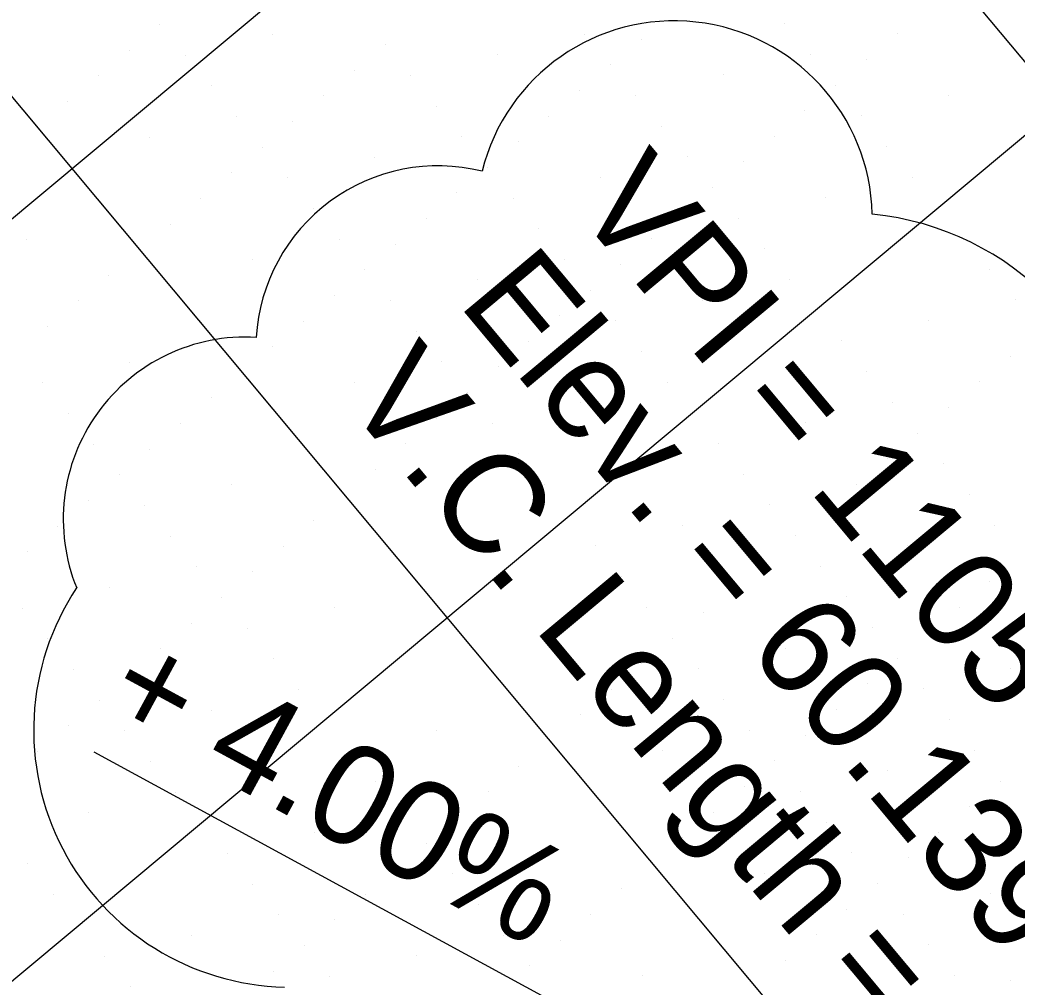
# Model space of a CAD drawing. Extents: x 2042995 to 2043795, y 305365 to 306249.
# Drawn here: x 2043332.63 to 2043357.56, y 305814.05 to 305838.24 of the extents above; entities that cross this region are included whole.
import ezdxf

# ---------------------------------------------------------------- set-up
doc = ezdxf.new("R2010")
doc.units = 0
for name, color, linetype in [('BR_CENTER LINES', 7, 'Continuous'), ('BR_CONCRETE', 7, 'Continuous'), ('BR_GRID DOTS', 7, 'Continuous'), ('BR_GRID LINES', 7, 'Continuous'), ('BR_PRESTRESSED BEAM', 7, 'Continuous'), ('BR_SITE LOCATION', 7, 'Continuous'), ('BR_TABLE LINES', 7, 'Continuous'), ('BR_TEXT', 7, 'Continuous')]:
    doc.layers.add(name, color=color, linetype=linetype)

msp = doc.modelspace()

# ---------------------------------------------------------------- linework, layer by layer
at = {"layer": 'BR_CENTER LINES'}
msp.add_line((2043349.78, 305847.751), (2043253.934, 305767.702), dxfattribs=at)
at = {"layer": 'BR_CONCRETE'}
for points in [[(2043139.109, 306017.548), (2043148.199, 306007.16), (2043160.233, 305993.368), (2043172.245, 305979.557), (2043184.234, 305965.727), (2043196.201, 305951.879), (2043208.145, 305938.012), (2043220.067, 305924.126), (2043231.966, 305910.221), (2043243.843, 305896.297), (2043255.698, 305882.355), (2043267.529, 305868.394), (2043279.339, 305854.414), (2043291.126, 305840.415), (2043302.89, 305826.398), (2043314.632, 305812.361), (2043326.352, 305798.306), (2043338.049, 305784.233), (2043349.724, 305770.14), (2043361.376, 305756.029), (2043373.005, 305741.899), (2043384.613, 305727.75), (2043396.197, 305713.582), (2043407.76, 305699.396), (2043419.299, 305685.191), (2043430.817, 305670.967), (2043442.311, 305656.724), (2043453.784, 305642.463), (2043465.234, 305628.182), (2043476.661, 305613.883), (2043488.066, 305599.566), (2043499.448, 305585.229), (2043510.808, 305570.874), (2043522.146, 305556.5), (2043533.461, 305542.107), (2043544.753, 305527.695), (2043547.219, 305524.543)], [(2043273.14, 305860.139), (2043278.86, 305853.362), (2043290.647, 305839.364), (2043302.411, 305825.346), (2043314.153, 305811.31), (2043325.873, 305797.255), (2043337.57, 305783.181), (2043349.245, 305769.089), (2043360.897, 305754.977), (2043372.526, 305740.847), (2043384.134, 305726.698), (2043395.718, 305712.531), (2043407.281, 305698.344), (2043418.82, 305684.139), (2043425.623, 305675.744)]]:
    msp.add_spline(points, degree=3, dxfattribs=at)
at = {"layer": 'BR_GRID DOTS'}
for p, q in [((2043336.123, 305838.127), (2043336.123, 305838.127)), ((2043351.743, 305838.144), (2043351.743, 305838.144)), ((2043338.94, 305837.874), (2043338.94, 305837.874)), ((2043346.75, 305837.883), (2043346.75, 305837.883)), ((2043354.561, 305837.892), (2043354.561, 305837.892)), ((2043341.757, 305837.621), (2043341.757, 305837.621)), ((2043348.159, 305837.756), (2043348.159, 305837.756)), ((2043335.355, 305837.486), (2043335.355, 305837.486)), ((2043336.764, 305837.36), (2043336.764, 305837.36)), ((2043344.574, 305837.368), (2043344.574, 305837.368)), ((2043352.385, 305837.377), (2043352.385, 305837.377)), ((2043347.391, 305837.115), (2043347.391, 305837.115)), ((2043353.793, 305837.25), (2043353.793, 305837.25)), ((2043334.588, 305836.845), (2043334.588, 305836.845)), ((2043340.99, 305836.98), (2043340.99, 305836.98)), ((2043342.398, 305836.854), (2043342.398, 305836.854)), ((2043350.208, 305836.862), (2043350.208, 305836.862)), ((2043337.405, 305836.592), (2043337.405, 305836.592)), ((2043353.026, 305836.609), (2043353.026, 305836.609)), ((2043340.222, 305836.339), (2043340.222, 305836.339)), ((2043346.624, 305836.474), (2043346.624, 305836.474)), ((2043348.032, 305836.348), (2043348.032, 305836.348)), ((2043355.843, 305836.356), (2043355.843, 305836.356)), ((2043333.82, 305836.204), (2043333.82, 305836.204)), ((2043343.039, 305836.086), (2043343.039, 305836.086)), ((2043338.046, 305835.825), (2043338.046, 305835.825)), ((2043345.856, 305835.833), (2043345.856, 305835.833)), ((2043352.258, 305835.968), (2043352.258, 305835.968)), ((2043353.667, 305835.842), (2043353.667, 305835.842)), ((2043333.053, 305835.563), (2043333.053, 305835.563)), ((2043339.455, 305835.698), (2043339.455, 305835.698)), ((2043348.673, 305835.58), (2043348.673, 305835.58)), ((2043335.87, 305835.31), (2043335.87, 305835.31)), ((2043343.68, 305835.319), (2043343.68, 305835.319)), ((2043351.491, 305835.327), (2043351.491, 305835.327)), ((2043338.687, 305835.057), (2043338.687, 305835.057)), ((2043345.089, 305835.192), (2043345.089, 305835.192)), ((2043354.308, 305835.074), (2043354.308, 305835.074)), ((2043341.504, 305834.804), (2043341.504, 305834.804)), ((2043349.314, 305834.813), (2043349.314, 305834.813)), ((2043344.321, 305834.551), (2043344.321, 305834.551)), ((2043350.723, 305834.686), (2043350.723, 305834.686)), ((2043337.92, 305834.416), (2043337.92, 305834.416)), ((2043339.328, 305834.29), (2043339.328, 305834.29)), ((2043347.138, 305834.298), (2043347.138, 305834.298)), ((2043354.949, 305834.307), (2043354.949, 305834.307)), ((2043349.955, 305834.045), (2043349.955, 305834.045)), ((2043343.554, 305833.91), (2043343.554, 305833.91)), ((2043344.962, 305833.784), (2043344.962, 305833.784)), ((2043352.773, 305833.792), (2043352.773, 305833.792)), ((2043337.152, 305833.775), (2043337.152, 305833.775)), ((2043339.969, 305833.522), (2043339.969, 305833.522)), ((2043349.188, 305833.404), (2043349.188, 305833.404)), ((2043336.385, 305833.134), (2043336.385, 305833.134)), ((2043342.786, 305833.269), (2043342.786, 305833.269)), ((2043350.597, 305833.278), (2043350.597, 305833.278)), ((2043345.603, 305833.016), (2043345.603, 305833.016)), ((2043332.8, 305832.746), (2043332.8, 305832.746)), ((2043340.61, 305832.755), (2043340.61, 305832.755)), ((2043342.019, 305832.628), (2043342.019, 305832.628)), ((2043348.42, 305832.763), (2043348.42, 305832.763)), ((2043356.231, 305832.772), (2043356.231, 305832.772)), ((2043335.617, 305832.493), (2043335.617, 305832.493)), ((2043351.238, 305832.51), (2043351.238, 305832.51)), ((2043338.434, 305832.24), (2043338.434, 305832.24)), ((2043346.244, 305832.249), (2043346.244, 305832.249)), ((2043347.653, 305832.122), (2043347.653, 305832.122)), ((2043334.85, 305831.852), (2043334.85, 305831.852)), ((2043341.251, 305831.987), (2043341.251, 305831.987)), ((2043356.872, 305832.004), (2043356.872, 305832.004)), ((2043344.068, 305831.734), (2043344.068, 305831.734)), ((2043351.879, 305831.743), (2043351.879, 305831.743)), ((2043340.484, 305831.346), (2043340.484, 305831.346)), ((2043346.885, 305831.481), (2043346.885, 305831.481)), ((2043334.082, 305831.211), (2043334.082, 305831.211)), ((2043341.892, 305831.22), (2043341.892, 305831.22)), ((2043349.702, 305831.228), (2043349.702, 305831.228)), ((2043357.513, 305831.237), (2043357.513, 305831.237)), ((2043346.118, 305830.84), (2043346.118, 305830.84)), ((2043333.314, 305830.57), (2043333.314, 305830.57)), ((2043339.716, 305830.705), (2043339.716, 305830.705)), ((2043347.526, 305830.714), (2043347.526, 305830.714)), ((2043355.337, 305830.722), (2043355.337, 305830.722)), ((2043342.533, 305830.452), (2043342.533, 305830.452)), ((2043338.949, 305830.064), (2043338.949, 305830.064)), ((2043345.35, 305830.199), (2043345.35, 305830.199)), ((2043353.161, 305830.208), (2043353.161, 305830.208)), ((2043348.167, 305829.946), (2043348.167, 305829.946)), ((2043357.386, 305829.828), (2043357.386, 305829.828)), ((2043335.364, 305829.676), (2043335.364, 305829.676)), ((2043343.174, 305829.685), (2043343.174, 305829.685)), ((2043344.583, 305829.558), (2043344.583, 305829.558)), ((2043338.181, 305829.423), (2043338.181, 305829.423)), ((2043353.802, 305829.44), (2043353.802, 305829.44)), ((2043333.188, 305829.162), (2043333.188, 305829.162)), ((2043340.998, 305829.17), (2043340.998, 305829.17)), ((2043348.808, 305829.179), (2043348.808, 305829.179)), ((2043356.619, 305829.187), (2043356.619, 305829.187)), ((2043343.815, 305828.917), (2043343.815, 305828.917)), ((2043337.414, 305828.782), (2043337.414, 305828.782)), ((2043346.632, 305828.664), (2043346.632, 305828.664)), ((2043354.443, 305828.673), (2043354.443, 305828.673)), ((2043355.851, 305828.546), (2043355.851, 305828.546)), ((2043333.829, 305828.394), (2043333.829, 305828.394)), ((2043336.646, 305828.141), (2043336.646, 305828.141)), ((2043343.048, 305828.276), (2043343.048, 305828.276)), ((2043344.456, 305828.15), (2043344.456, 305828.15)), ((2043352.267, 305828.158), (2043352.267, 305828.158)), ((2043355.084, 305827.905), (2043355.084, 305827.905)), ((2043334.47, 305827.627), (2043334.47, 305827.627)), ((2043342.28, 305827.635), (2043342.28, 305827.635)), ((2043350.091, 305827.644), (2043350.091, 305827.644)), ((2043335.879, 305827.5), (2043335.879, 305827.5)), ((2043345.097, 305827.382), (2043345.097, 305827.382)), ((2043354.316, 305827.264), (2043354.316, 305827.264)), ((2043355.725, 305827.138), (2043355.725, 305827.138)), ((2043335.111, 305826.859), (2043335.111, 305826.859)), ((2043341.513, 305826.994), (2043341.513, 305826.994)), ((2043350.732, 305826.876), (2043350.732, 305826.876)), ((2043337.928, 305826.606), (2043337.928, 305826.606)), ((2043345.738, 305826.615), (2043345.738, 305826.615)), ((2043353.549, 305826.623), (2043353.549, 305826.623)), ((2043340.745, 305826.353), (2043340.745, 305826.353)), ((2043356.366, 305826.37), (2043356.366, 305826.37)), ((2043334.344, 305826.218), (2043334.344, 305826.218)), ((2043335.752, 305826.091), (2043335.752, 305826.091)), ((2043343.562, 305826.1), (2043343.562, 305826.1)), ((2043351.373, 305826.109), (2043351.373, 305826.109)), ((2043352.781, 305825.982), (2043352.781, 305825.982)), ((2043333.576, 305825.577), (2043333.576, 305825.577)), ((2043339.978, 305825.712), (2043339.978, 305825.712)), ((2043349.197, 305825.594), (2043349.197, 305825.594)), ((2043357.007, 305825.603), (2043357.007, 305825.603)), ((2043336.393, 305825.324), (2043336.393, 305825.324)), ((2043352.014, 305825.341), (2043352.014, 305825.341)), ((2043339.21, 305825.071), (2043339.21, 305825.071)), ((2043347.02, 305825.08), (2043347.02, 305825.08)), ((2043354.831, 305825.088), (2043354.831, 305825.088)), ((2043332.809, 305824.936), (2043332.809, 305824.936)), ((2043337.034, 305824.556), (2043337.034, 305824.556)), ((2043351.246, 305824.7), (2043351.246, 305824.7)), ((2043352.655, 305824.574), (2043352.655, 305824.574)), ((2043338.443, 305824.43), (2043338.443, 305824.43)), ((2043347.661, 305824.312), (2043347.661, 305824.312)), ((2043350.479, 305824.059), (2043350.479, 305824.059)), ((2043356.88, 305824.194), (2043356.88, 305824.194)), ((2043334.858, 305824.042), (2043334.858, 305824.042)), ((2043353.296, 305823.806), (2043353.296, 305823.806)), ((2043337.675, 305823.789), (2043337.675, 305823.789)), ((2043332.682, 305823.527), (2043332.682, 305823.527)), ((2043340.492, 305823.536), (2043340.492, 305823.536)), ((2043348.303, 305823.545), (2043348.303, 305823.545)), ((2043349.711, 305823.418), (2043349.711, 305823.418)), ((2043356.113, 305823.553), (2043356.113, 305823.553)), ((2043336.908, 305823.148), (2043336.908, 305823.148)), ((2043338.316, 305823.021), (2043338.316, 305823.021)), ((2043346.126, 305823.03), (2043346.126, 305823.03)), ((2043353.937, 305823.039), (2043353.937, 305823.039)), ((2043355.345, 305822.912), (2043355.345, 305822.912)), ((2043333.323, 305822.76), (2043333.323, 305822.76)), ((2043348.944, 305822.777), (2043348.944, 305822.777)), ((2043336.14, 305822.507), (2043336.14, 305822.507)), ((2043351.761, 305822.524), (2043351.761, 305822.524)), ((2043338.957, 305822.254), (2043338.957, 305822.254)), ((2043348.176, 305822.136), (2043348.176, 305822.136)), ((2043354.578, 305822.271), (2043354.578, 305822.271)), ((2043333.964, 305821.992), (2043333.964, 305821.992)), ((2043335.373, 305821.866), (2043335.373, 305821.866)), ((2043349.585, 305822.009), (2043349.585, 305822.009)), ((2043357.395, 305822.018), (2043357.395, 305822.018)), ((2043353.81, 305821.63), (2043353.81, 305821.63)), ((2043339.598, 305821.486), (2043339.598, 305821.486)), ((2043347.408, 305821.495), (2043347.408, 305821.495)), ((2043355.219, 305821.504), (2043355.219, 305821.504)), ((2043334.605, 305821.225), (2043334.605, 305821.225)), ((2043350.226, 305821.242), (2043350.226, 305821.242)), ((2043337.422, 305820.972), (2043337.422, 305820.972)), ((2043346.641, 305820.854), (2043346.641, 305820.854)), ((2043353.043, 305820.989), (2043353.043, 305820.989)), ((2043333.838, 305820.584), (2043333.838, 305820.584)), ((2043355.86, 305820.736), (2043355.86, 305820.736)), ((2043335.246, 305820.457), (2043335.246, 305820.457)), ((2043343.056, 305820.466), (2043343.056, 305820.466)), ((2043350.867, 305820.474), (2043350.867, 305820.474)), ((2043352.275, 305820.348), (2043352.275, 305820.348)), ((2043345.873, 305820.213), (2043345.873, 305820.213)), ((2043333.07, 305819.943), (2043333.07, 305819.943)), ((2043340.88, 305819.951), (2043340.88, 305819.951)), ((2043348.691, 305819.96), (2043348.691, 305819.96)), ((2043356.501, 305819.968), (2043356.501, 305819.968)), ((2043335.887, 305819.69), (2043335.887, 305819.69)), ((2043345.106, 305819.572), (2043345.106, 305819.572)), ((2043351.508, 305819.707), (2043351.508, 305819.707)), ((2043354.325, 305819.454), (2043354.325, 305819.454)), ((2043341.521, 305819.184), (2043341.521, 305819.184)), ((2043357.142, 305819.201), (2043357.142, 305819.201)), ((2043336.528, 305818.922), (2043336.528, 305818.922)), ((2043344.338, 305818.931), (2043344.338, 305818.931)), ((2043350.74, 305819.066), (2043350.74, 305819.066)), ((2043352.149, 305818.939), (2043352.149, 305818.939)), ((2043334.352, 305818.408), (2043334.352, 305818.408)), ((2043342.162, 305818.416), (2043342.162, 305818.416)), ((2043349.973, 305818.425), (2043349.973, 305818.425)), ((2043356.374, 305818.56), (2043356.374, 305818.56)), ((2043343.571, 305818.29), (2043343.571, 305818.29)), ((2043352.79, 305818.172), (2043352.79, 305818.172)), ((2043339.986, 305817.902), (2043339.986, 305817.902)), ((2043355.607, 305817.919), (2043355.607, 305817.919)), ((2043342.803, 305817.649), (2043342.803, 305817.649)), ((2043349.205, 305817.784), (2043349.205, 305817.784)), ((2043337.81, 305817.387), (2043337.81, 305817.387)), ((2043345.62, 305817.396), (2043345.62, 305817.396)), ((2043353.431, 305817.404), (2043353.431, 305817.404)), ((2043332.817, 305817.126), (2043332.817, 305817.126)), ((2043348.438, 305817.143), (2043348.438, 305817.143)), ((2043354.839, 305817.278), (2043354.839, 305817.278)), ((2043342.036, 305817.008), (2043342.036, 305817.008)), ((2043343.444, 305816.881), (2043343.444, 305816.881)), ((2043351.255, 305816.89), (2043351.255, 305816.89)), ((2043338.451, 305816.62), (2043338.451, 305816.62)), ((2043354.072, 305816.637), (2043354.072, 305816.637)), ((2043333.458, 305816.358), (2043333.458, 305816.358)), ((2043341.268, 305816.367), (2043341.268, 305816.367)), ((2043347.67, 305816.502), (2043347.67, 305816.502)), ((2043356.889, 305816.384), (2043356.889, 305816.384)), ((2043344.085, 305816.114), (2043344.085, 305816.114)), ((2043339.092, 305815.852), (2043339.092, 305815.852)), ((2043346.903, 305815.861), (2043346.903, 305815.861)), ((2043353.304, 305815.996), (2043353.304, 305815.996)), ((2043354.713, 305815.869), (2043354.713, 305815.869)), ((2043340.501, 305815.726), (2043340.501, 305815.726)), ((2043336.916, 305815.338), (2043336.916, 305815.338)), ((2043344.726, 305815.346), (2043344.726, 305815.346)), ((2043352.537, 305815.355), (2043352.537, 305815.355)), ((2043339.733, 305815.085), (2043339.733, 305815.085)), ((2043346.135, 305815.22), (2043346.135, 305815.22)), ((2043355.354, 305815.102), (2043355.354, 305815.102)), ((2043342.55, 305814.832), (2043342.55, 305814.832)), ((2043334.74, 305814.823), (2043334.74, 305814.823)), ((2043345.367, 305814.579), (2043345.367, 305814.579)), ((2043351.769, 305814.714), (2043351.769, 305814.714)), ((2043338.966, 305814.444), (2043338.966, 305814.444)), ((2043355.995, 305814.334), (2043355.995, 305814.334)), ((2043340.374, 305814.317), (2043340.374, 305814.317)), ((2043348.185, 305814.326), (2043348.185, 305814.326)), ((2043357.403, 305814.208), (2043357.403, 305814.208)), ((2043335.381, 305814.056), (2043335.381, 305814.056)), ((2043351.002, 305814.073), (2043351.002, 305814.073))]:
    msp.add_line(p, q, dxfattribs=at)
at = {"layer": 'BR_GRID LINES'}
for p, q in [((2043168.489, 306063.801), (2043600.112, 305547.005)), ((2043153.138, 306050.98), (2043584.762, 305534.185)), ((2043374.01, 305848.924), (2043220.506, 305720.719))]:
    msp.add_line(p, q, dxfattribs=at)
at = {"layer": 'BR_PRESTRESSED BEAM'}
msp.add_spline([(2043269.336, 305856.962), (2043274.734, 305850.568), (2043286.521, 305836.569), (2043298.285, 305822.551), (2043310.027, 305808.515), (2043321.747, 305794.46), (2043333.444, 305780.386), (2043345.119, 305766.294), (2043356.771, 305752.183), (2043368.4, 305738.053), (2043380.007, 305723.904), (2043391.592, 305709.736), (2043403.154, 305695.55), (2043414.694, 305681.345), (2043421.811, 305672.561)], degree=3, dxfattribs=at)
at = {"layer": 'BR_SITE LOCATION'}
msp.add_line((2043348.342, 305812.385), (2043334.483, 305819.921), dxfattribs=at)
at = {"layer": 'BR_TABLE LINES'}
for centre, radius, start, end in [((2043348.99, 305833.264), 4.952, 1.3526, 166.0745), ((2043343.086, 305830.031), 4.558, 76.0745, 176.6309), ((2043353.215, 305826.18), 7.237, 3.9091, 84.2446), ((2043338.268, 305825.748), 4.558, 86.6309, 202.1428), ((2043339.397, 305820.471), 6.427, 146.3744, 268.6484)]:
    msp.add_arc(centre, radius, start, end, dxfattribs=at)

# ---------------------------------------------------------------- texts
at = {"layer": 'BR_TEXT'}
for s, rotation, p in [('VPI = 1105+70.00', 309.8684, (2043346.437, 305833.549)), ('Elev. = 60.139', 309.8684, (2043343.559, 305831.145)), ("V.C. Length = 915.00'", 309.8684, (2043340.681, 305828.741)), ('+ 4.00%', 331.4665, (2043334.594, 305820.904))]:
    msp.add_text(s, height=2.5, rotation=rotation, dxfattribs=at).set_placement(p)

doc.saveas('drawing.dxf')
